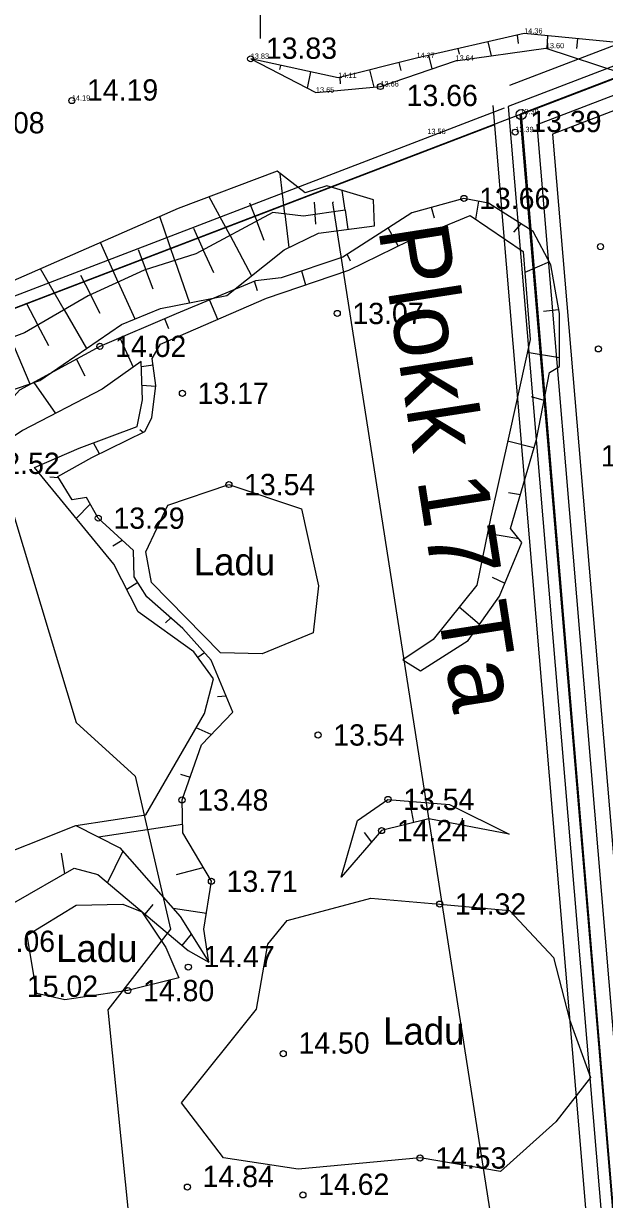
# Model space of a CAD drawing. Extents: x 433497 to 434382, y 6534486 to 6534993.
# Drawn here: x 433584.4 to 433622.7, y 6534719.6 to 6534797 of the extents above; entities that cross this region are included whole.
import ezdxf

# ---------------------------------------------------------------- set-up
doc = ezdxf.new("R2010")
doc.units = 0
for name, color, linetype in [('Default', 7, 'Continuous'), ('kataster', 7, 'Continuous'), ('KORGUS-EH2000', 7, 'Continuous'), ('MOOTKORG-EH2000', 7, 'Continuous'), ('PIIR', 7, 'Continuous'), ('RELJEEF', 7, 'Continuous'), ('VEEKOGU', 7, 'Continuous'), ('VORK', 7, 'Continuous'), ('VORMISTUS', 7, 'Continuous')]:
    doc.layers.add(name, color=color, linetype=linetype)

msp = doc.modelspace()

# ---------------------------------------------------------------- linework, layer by layer
at = {"layer": 'Default'}
msp.add_lwpolyline([(433617.12, 6534791.025), (433632.75, 6534606.045), (434137.38, 6534796.515), (434127.69, 6534855.6), (433968.21, 6534911.925), (433942.38, 6534904.035), (433920.99, 6534907.275)], close=True, dxfattribs=at)
msp.add_lwpolyline([(433617.12, 6534791.025), (433632.75, 6534606.045), (434137.38, 6534796.515), (434127.69, 6534855.6), (433968.21, 6534911.925), (433942.38, 6534904.035), (433920.99, 6534907.275)], close=True, dxfattribs=at)
msp.add_lwpolyline([(433617.12, 6534791.025), (433632.75, 6534606.045), (434137.38, 6534796.515), (434127.69, 6534855.6), (433968.21, 6534911.925), (433942.38, 6534904.035), (433920.99, 6534907.275)], close=True, dxfattribs=at)
at = {"layer": 'kataster'}
msp.add_lwpolyline([(433617.102, 6534791.002), (433632.769, 6534606.029), (434137.446, 6534796.469), (434127.827, 6534855.589), (433950.026, 6534918.39)], close=True, dxfattribs=at)
msp.add_lwpolyline([(433658.341, 6534546.765), (433632.769, 6534606.029), (433617.102, 6534791.002), (433580.107, 6534776.838)], dxfattribs=at)
at = {"layer": 'KORGUS-EH2000'}
for centre in [(433599.373, 6534794.656), (433607.913, 6534792.835), (433587.602, 6534791.91), (433616.783, 6534789.835), (433613.408, 6534785.475), (433622.398, 6534782.302), (433605.07, 6534777.91), (433589.447, 6534775.747), (433622.259, 6534775.578), (433594.88, 6534772.66), (433597.94, 6534766.66), (433589.34, 6534764.448), (433603.81, 6534750.19), (433594.854, 6534745.915), (433608.41, 6534745.95), (433607.99, 6534743.9), (433596.791, 6534740.569), (433611.82, 6534739.07), (433595.268, 6534734.921), (433591.29, 6534733.38), (433601.518, 6534729.233), (433610.52, 6534722.37), (433595.212, 6534720.457), (433602.813, 6534719.944)]:
    msp.add_circle(centre, 0.2, dxfattribs=at)
at = {"layer": 'PIIR'}
for points in [[(433632.021, 6534604.835), (434138.248, 6534795.936), (434128.468, 6534856.135), (433968.226, 6534912.818), (433942.33, 6534904.85), (433920.952, 6534908.165), (433616.327, 6534791.524), (433632.021, 6534604.835)], [(433632.732, 6534605.959), (434137.353, 6534796.454), (434127.754, 6534855.539), (433968.208, 6534911.976), (433942.39, 6534904.031), (433921.04, 6534907.341), (433617.174, 6534790.992), (433632.732, 6534605.959)], [(433616.435, 6534792.923), (433775.118, 6534853.561)], [(433616.055, 6534791.42), (433579.812, 6534777.508)], [(433615.318, 6534791.592), (433631.004, 6534605.083)], [(433615.414, 6534790.319), (433580.109, 6534776.809)], [(433604.829, 6534785.219), (433604.764, 6534785.194), (433627.432, 6534640.09)]]:
    msp.add_lwpolyline(points, dxfattribs=at)
for points in [[(433618.234, 6534790.327), (433921.149, 6534906.313), (433942.464, 6534903.008), (433968.187, 6534910.923), (434126.862, 6534854.794), (434136.235, 6534797.101), (433633.617, 6534607.362)], [(433619.24, 6534789.695), (433634.52, 6534608.851), (434135.141, 6534797.808), (434125.908, 6534854.108), (433968.165, 6534909.82), (433942.53, 6534901.99), (433921.212, 6534905.219)], [(433619.24, 6534789.695), (433634.52, 6534608.851), (434135.141, 6534797.808), (434125.908, 6534854.108), (433968.165, 6534909.82), (433942.53, 6534901.99), (433921.212, 6534905.219)]]:
    msp.add_lwpolyline(points, close=True, dxfattribs=at)
msp.add_circle((433617.174, 6534790.992), 0.325, dxfattribs=at)
at = {"layer": 'RELJEEF'}
for p, q in [((433614.987, 6534795.775), (433615.196, 6534794.856)), ((433616.992, 6534795.665), (433616.937, 6534796.22)), ((433618.919, 6534796.171), (433618.868, 6534795.329)), ((433620.848, 6534795.34), (433620.909, 6534795.98)), ((433611.087, 6534794.886), (433611.296, 6534793.998)), ((433613.122, 6534794.957), (433613.037, 6534795.331)), ((433599.373, 6534794.656), (433599.373, 6534794.656)), ((433599.402, 6534794.65), (433599.401, 6534794.642)), ((433601.299, 6534793.959), (433601.357, 6534794.226)), ((433607.204, 6534793.926), (433607.489, 6534792.795)), ((433609.275, 6534793.882), (433609.143, 6534794.415)), ((433603.311, 6534793.802), (433603.096, 6534792.734)), ((433605.278, 6534793.014), (433605.265, 6534793.437)), ((433601.63, 6534784.455), (433601.32, 6534787.1)), ((433598.016, 6534783.036), (433596.651, 6534785.58)), ((433605.592, 6534784.71), (433605.403, 6534786.001)), ((433599.306, 6534785.192), (433599.778, 6534783.981)), ((433603.562, 6534785.223), (433603.613, 6534784.42)), ((433605.592, 6534784.71), (433605.777, 6534783.448)), ((433611.482, 6534784.182), (433611.275, 6534784.886)), ((433614.378, 6534785.29), (433614.165, 6534784.115)), ((433594.386, 6534781.393), (433593.392, 6534784.277)), ((433600.27, 6534782.717), (433599.778, 6534783.981)), ((433601.63, 6534784.455), (433601.888, 6534782.251)), ((433603.655, 6534783.774), (433603.613, 6534784.42)), ((433595.607, 6534783.517), (433596.253, 6534782.091)), ((433608.415, 6534783.53), (433609.073, 6534782.344)), ((433616.703, 6534783.259), (433617.171, 6534783.805)), ((433590.653, 6534779.977), (433589.487, 6534782.568)), ((433598.016, 6534783.036), (433599.432, 6534780.394)), ((433591.977, 6534782.114), (433592.479, 6534780.79)), ((433596.94, 6534780.574), (433596.253, 6534782.091)), ((433605.941, 6534781.36), (433605.72, 6534781.805)), ((433587.097, 6534778.156), (433585.544, 6534780.841)), ((433592.962, 6534779.517), (433592.479, 6534780.79)), ((433594.386, 6534781.393), (433595.344, 6534778.614)), ((433619.034, 6534781.309), (433617.421, 6534780.595)), ((433588.177, 6534780.428), (433588.832, 6534779.15)), ((433599.819, 6534779.389), (433599.616, 6534780.033)), ((433602.725, 6534780.703), (433602.99, 6534779.79)), ((433590.653, 6534779.977), (433591.746, 6534777.547)), ((433584.593, 6534778.616), (433585.37, 6534777.147)), ((433589.469, 6534777.906), (433588.832, 6534779.15)), ((433596.666, 6534778.795), (433597.199, 6534777.525)), ((433587.097, 6534778.156), (433588.571, 6534775.609)), ((433618.635, 6534778.071), (433619.643, 6534778.178)), ((433586.096, 6534775.777), (433585.37, 6534777.147)), ((433593.99, 6534776.905), (433593.716, 6534777.554)), ((433583.572, 6534776.289), (433584.848, 6534773.274)), ((433590.769, 6534776.307), (433591.647, 6534774.383)), ((433590.769, 6534776.307), (433591.647, 6534774.383)), ((433588.479, 6534773.782), (433587.899, 6534774.9)), ((433588.479, 6534773.782), (433587.899, 6534774.9)), ((433619.704, 6534774.982), (433617.576, 6534775.342)), ((433592.961, 6534774.503), (433592.179, 6534774.397)), ((433585.092, 6534773.365), (433586.518, 6534771.334)), ((433585.092, 6534773.365), (433586.518, 6534771.334)), ((433593.131, 6534773.1), (433592.219, 6534773.163)), ((433617.833, 6534772.45), (433618.676, 6534772.206)), ((433592.073, 6534770.282), (433592.289, 6534770.103)), ((433589.419, 6534768.688), (433589.033, 6534769.409)), ((433618.016, 6534769.077), (433616.285, 6534769.509)), ((433586.165, 6534767.177), (433586.721, 6534767.129)), ((433616.344, 6534766.127), (433617.126, 6534766.003)), ((433588.815, 6534765.376), (433587.898, 6534764.433)), ((433590.294, 6534762.637), (433590.913, 6534763.007)), ((433617.033, 6534763.088), (433614.954, 6534763.447)), ((433591.946, 6534760.209), (433591.221, 6534759.762)), ((433615.269, 6534760.565), (433616.103, 6534760.183)), ((433614.442, 6534757.465), (433613.086, 6534758.599)), ((433593.77, 6534757.564), (433594.111, 6534757.888)), ((433596.336, 6534755.595), (433595.893, 6534755.281)), ((433597.186, 6534752.729), (433597.75, 6534752.757)), ((433596.783, 6534750.218), (433595.792, 6534750.653)), ((433594.759, 6534747.607), (433595.381, 6534747.408)), ((433610.118, 6534744.435), (433609.849, 6534745.829)), ((433613.303, 6534744.713), (433613.248, 6534744.265)), ((433594.892, 6534744.299), (433589.352, 6534743.48)), ((433606.845, 6534743.786), (433607.33, 6534743.141)), ((433586.896, 6534742.41), (433587.109, 6534741.06)), ((433589.958, 6534740.465), (433590.963, 6534742.536)), ((433594.49, 6534741.005), (433596.257, 6534741.47)), ((433605.32, 6534740.83), (433605.32, 6534740.83)), ((433592.944, 6534739.045), (433592.408, 6534738.407)), ((433596.455, 6534738.442), (433594.269, 6534738.788)), ((433594.858, 6534736.349), (433595.477, 6534737.085))]:
    msp.add_line(p, q, dxfattribs=at)
for points in [[(433630.892, 6534795.453), (433623.697, 6534795.713), (433617.372, 6534796.319), (433610.285, 6534794.703), (433605.139, 6534793.405), (433599.373, 6534794.656)], [(433599.373, 6534794.656), (433603.668, 6534792.439), (433607.913, 6534792.835), (433612.854, 6534794.534), (433618.799, 6534795.352), (433623.869, 6534793.691), (433630.892, 6534795.453)], [(433607.526, 6534783.677), (433607.462, 6534785.38), (433604.395, 6534786.305), (433602.961, 6534785.853), (433601.108, 6534787.261), (433594.611, 6534784.811), (433581.226, 6534778.951), (433574.866, 6534776.41)], [(433609.395, 6534755.135), (433610.547, 6534754.398), (433613.698, 6534756.399), (433615.743, 6534759.329), (433617.226, 6534762.848), (433616.482, 6534763.776), (433618.175, 6534769.628), (433619.03, 6534774.03), (433619.707, 6534774.422), (433619.688, 6534777.913), (433619.139, 6534781.114), (433617.955, 6534783.308), (433615.016, 6534785.169), (433613.408, 6534785.475), (433609.97, 6534784.525), (433605.433, 6534781.621), (433601.38, 6534780.247), (433599.682, 6534780.061), (433594.479, 6534777.877), (433589.447, 6534775.747), (433584.163, 6534772.857), (433582.314, 6534770.819), (433576.875, 6534768.834)], [(433605.592, 6534784.71), (433602.854, 6534784.309), (433600.837, 6534784.549), (433595.763, 6534781.828), (433592.356, 6534780.751), (433588.679, 6534779.08), (433584.478, 6534776.626), (433577.274, 6534773.95), (433576.094, 6534773.449)], [(433593.43, 6534775.895), (433600.415, 6534778.915), (433605.844, 6534780.759), (433609.783, 6534782.693), (433613.814, 6534784.353), (433617.311, 6534781.984), (433617.767, 6534776.205), (433616.403, 6534770.042), (433615.179, 6534764.53), (433614.248, 6534760.047), (433611.382, 6534756.476), (433609.395, 6534755.135)], [(433577.248, 6534770.666), (433585.495, 6534773.496), (433590.868, 6534777.187), (433593.444, 6534778.245), (433597.796, 6534779.09), (433601.572, 6534782.098), (433603.832, 6534783.194), (433607.526, 6534783.677)], [(433596.628, 6534735.259), (433596.294, 6534737.425), (433596.791, 6534740.569), (433594.905, 6534743.753), (433594.854, 6534745.915), (433596.138, 6534749.551), (433598.197, 6534751.68), (433596.771, 6534755.113), (433594.903, 6534757.183), (433592.549, 6534759.28), (433591.695, 6534760.595), (433591.658, 6534762.324), (433589.34, 6534764.448), (433588.567, 6534765.816), (433587.622, 6534765.646), (433586.679, 6534767.198), (433588.912, 6534768.438), (433592.399, 6534770.157), (433592.87, 6534771.037), (433593.141, 6534773.182), (433592.9, 6534774.952), (433593.43, 6534775.895)], [(433592.47, 6534762.24), (433593.91, 6534765.3), (433597.94, 6534766.66), (433602.71, 6534765.07), (433603.83, 6534759.99), (433603.48, 6534756.9), (433600.12, 6534755.52), (433597.38, 6534755.59), (433592.85, 6534760.21), (433592.47, 6534762.24)], [(433605.32, 6534740.83), (433606.4, 6534744.57), (433608.41, 6534745.95), (433612.45, 6534745.61), (433616.39, 6534743.66)], [(433616.39, 6534743.66), (433611.09, 6534744.68), (433607.99, 6534743.9), (433605.32, 6534740.83), (433605.32, 6534740.83)], [(433587.876, 6534744.229), (433590.759, 6534742.767), (433594.739, 6534738.255), (433596.628, 6534735.259)], [(433581.42, 6534738.148), (433583.776, 6534739.161), (433587.754, 6534741.427), (433589.304, 6534741.014), (433595.249, 6534736.021), (433596.628, 6534735.259)], [(433593.79, 6534736.22), (433594.65, 6534734.22), (433591.29, 6534733.38), (433587.15, 6534732.78), (433585.29, 6534733.18), (433584.67, 6534737.03), (433587.88, 6534738.99), (433590.96, 6534739.06), (433592.21, 6534738.56), (433593.79, 6534736.22)], [(433611.82, 6534739.07), (433616.41, 6534738.64), (433619.3, 6534735.56), (433620.36, 6534731.47), (433621.73, 6534727.66), (433619.45, 6534724.74), (433615.81, 6534721.49), (433610.52, 6534722.37), (433602.49, 6534721.64), (433597.58, 6534722.38), (433594.82, 6534726), (433599.75, 6534732.15), (433600.5, 6534736.43), (433601.77, 6534737.99), (433607.29, 6534739.46), (433611.82, 6534739.07)], [(433611.82, 6534739.07), (433616.41, 6534738.64), (433619.3, 6534735.56), (433620.36, 6534731.47), (433621.73, 6534727.66), (433619.45, 6534724.74), (433615.81, 6534721.49), (433610.52, 6534722.37), (433602.49, 6534721.64), (433597.58, 6534722.38), (433594.82, 6534726), (433599.75, 6534732.15), (433600.5, 6534736.43), (433601.77, 6534737.99), (433607.29, 6534739.46), (433611.82, 6534739.07)]]:
    msp.add_lwpolyline(points, dxfattribs=at)
at = {"layer": 'VEEKOGU'}
msp.add_lwpolyline([(433581.45, 6534741.702), (433587.876, 6534744.229), (433592.471, 6534744.941), (433596.344, 6534751.602), (433596.92, 6534753.873), (433595.626, 6534755.647), (433591.976, 6534758.292), (433590.369, 6534761.421), (433585.155, 6534767.778), (433588.085, 6534769.056), (433591.892, 6534770.473), (433592.249, 6534772.222), (433592.168, 6534774.748), (433589.589, 6534772.942), (433584.362, 6534770.204), (433581.121, 6534768.057), (433577.589, 6534766.798)], dxfattribs=at)
at = {"layer": 'VORK'}
msp.add_line((433600, 6534804), (433600, 6534796), dxfattribs=at)
at = {"layer": 'VORMISTUS'}
msp.add_lwpolyline([(433756.833, 6534894.348), (433691.203, 6534872.087), (433653.508, 6534864.187), (433636.546, 6534862.392), (433627.673, 6534847.824), (433564.128, 6534829.695), (433582.608, 6534768.478), (433587.883, 6534751.004), (433591.763, 6534747.472), (433594.096, 6534737.418), (433589.968, 6534732.121), (433592.57, 6534706.447), (433596.133, 6534671.303), (433599.93, 6534613.558), (433630.448, 6534534.937), (433664.149, 6534549.227), (433704.536, 6534572.568), (433752.081, 6534596.222), (433789.501, 6534614.839)], dxfattribs=at)
msp.add_lwpolyline([(433756.833, 6534894.348), (433691.203, 6534872.087), (433653.508, 6534864.187), (433636.546, 6534862.392), (433627.673, 6534847.824), (433564.128, 6534829.695), (433582.608, 6534768.478), (433587.883, 6534751.004), (433591.763, 6534747.472), (433594.096, 6534737.418), (433589.968, 6534732.121), (433592.57, 6534706.447), (433596.133, 6534671.303), (433599.93, 6534613.558), (433630.448, 6534534.937), (433664.149, 6534549.227), (433704.536, 6534572.568), (433752.081, 6534596.222), (433789.501, 6534614.839)], dxfattribs=at)

# ---------------------------------------------------------------- texts
at = {"layer": 'KORGUS-EH2000'}
for s, p in [('13.83', (433600.373, 6534794.656)), ('14.19', (433588.602, 6534791.91)), ('13.66', (433609.638, 6534791.548)), ('14.08', (433581.122, 6534789.754)), ('13.39', (433617.783, 6534789.835)), ('13.66', (433614.408, 6534784.775)), ('13.07', (433606.07, 6534777.21)), ('14.02', (433590.447, 6534775.047)), ('13.17', (433595.88, 6534771.96)), ('13.44', (433622.416, 6534767.847)), ('12.52', (433582.121, 6534767.357)), ('13.54', (433598.94, 6534765.96)), ('13.29', (433590.34, 6534763.748)), ('13.54', (433604.81, 6534749.49)), ('13.48', (433595.854, 6534745.215)), ('13.54', (433609.41, 6534745.25)), ('14.24', (433608.99, 6534743.2)), ('13.71', (433597.791, 6534739.869)), ('14.32', (433612.82, 6534738.37)), ('15.06', (433581.816, 6534735.922)), ('14.47', (433596.268, 6534734.921)), ('15.02', (433584.644, 6534732.967)), ('14.80', (433592.29, 6534732.68)), ('14.50', (433602.518, 6534729.233)), ('14.53', (433611.52, 6534721.67)), ('14.84', (433596.212, 6534720.457)), ('14.62', (433603.813, 6534719.944))]:
    msp.add_text(s, height=1.4, dxfattribs=at).set_placement(p)
at = {"layer": 'MOOTKORG-EH2000'}
for s, p in [('14.36', (433617.372, 6534796.319)), ('13.60', (433618.799, 6534795.352)), ('13.83', (433599.373, 6534794.656)), ('14.27', (433610.285, 6534794.703)), ('13.64', (433612.854, 6534794.534)), ('14.11', (433605.139, 6534793.405)), ('13.66', (433607.913, 6534792.835)), ('13.65', (433603.668, 6534792.439)), ('14.19', (433587.602, 6534791.91)), ('13.30', (433617.123, 6534791.009)), ('13.56', (433610.997, 6534789.708)), ('13.39', (433616.783, 6534789.835))]:
    msp.add_text(s, height=0.35, dxfattribs=at).set_placement(p)
at = {"layer": 'PIIR'}
msp.add_text('Plokk 17 Ta', height=4.58, rotation=278.86473, dxfattribs=at).set_placement((433607.755, 6534783.48))
msp.add_text('Plokk 17 Ta', height=4.58, rotation=278.86473, dxfattribs=at).set_placement((433607.755, 6534783.48))
at = {"layer": 'RELJEEF'}
for p in [(433595.632, 6534760.687), (433586.568, 6534735.256), (433608.089, 6534729.817)]:
    msp.add_text('Ladu', height=1.8, dxfattribs=at).set_placement(p)

doc.saveas('drawing.dxf')
